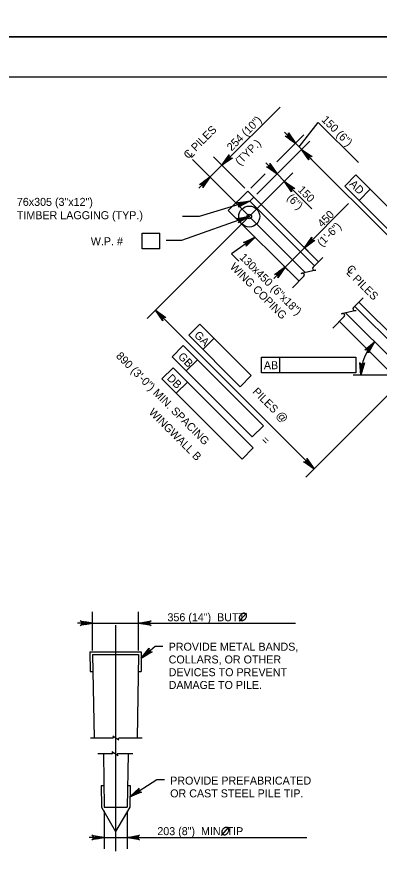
# Model space of a CAD drawing. Extents: x 635440 to 640306, y 296653 to 298484.
# Drawn here: x 638479.7 to 638615.6, y 296941.7 to 297255 of the extents above; entities that cross this region are included whole.
import ezdxf

# ---------------------------------------------------------------- set-up
doc = ezdxf.new("R2010")
doc.units = 0
for name, color, linetype in [('2', 7, 'Continuous'), ('4', 7, 'Continuous'), ('5', 7, 'Continuous'), ('52', 7, 'Continuous'), ('PLT-BNDY', 7, 'Continuous')]:
    doc.layers.add(name, color=color, linetype=linetype)

msp = doc.modelspace()

# ---------------------------------------------------------------- linework, layer by layer
at = {"layer": '2'}
for p, q in [((638475.46, 297232.46), (639261.46, 297232.46)), ((638566.31, 297189.6), (638559, 297182.3)), ((638592.81, 297163.11), (638566.31, 297189.6)), ((638585.5, 297155.8), (638559, 297182.3)), ((638627.92, 297128), (638607.92, 297148)), ((638623.64, 297117.66), (638600.61, 297140.69))]:
    msp.add_line(p, q, dxfattribs=at)
at = {"layer": '4'}
for p, q in [((638568.57, 297187.34), (638567.01, 297185.78)), ((638591.24, 297161.54), (638567.01, 297185.78)), ((638632.09, 297120.7), (638606.35, 297146.43)), ((638516.77, 297026.87), (638516.77, 296942.2)), ((638507.15, 297016.86), (638507.27, 297009.46)), ((638507.15, 297016.86), (638526.39, 297016.86)), ((638508.15, 297015.87), (638508.65, 296984.5)), ((638508.15, 297015.87), (638525.39, 297015.87)), ((638525.39, 297015.87), (638524.89, 296984.5)), ((638526.39, 297016.86), (638526.27, 297009.46)), ((638507.27, 297009.46), (638508.25, 297009.46)), ((638525.29, 297009.46), (638526.27, 297009.46)), ((638515.67, 296984.5), (638507.3, 296984.5)), ((638517.98, 296983.77), (638515.67, 296985.23)), ((638526.66, 296984.5), (638518, 296984.5)), ((638515.36, 296978.66), (638510.07, 296978.66)), ((638512.15, 296978.66), (638512.46, 296958.69)), ((638517.67, 296977.93), (638515.36, 296979.38)), ((638523.26, 296978.66), (638517.69, 296978.66)), ((638521.4, 296978.66), (638521.08, 296958.69)), ((638511.38, 296966.73), (638511.48, 296958.68)), ((638511.38, 296966.73), (638512.37, 296966.73)), ((638521.18, 296966.73), (638522.16, 296966.73)), ((638522.16, 296966.73), (638522.06, 296958.68)), ((638511.48, 296958.68), (638516.77, 296949.51)), ((638512.46, 296958.69), (638521.08, 296958.69)), ((638522.06, 296958.68), (638516.77, 296949.51))]:
    msp.add_line(p, q, dxfattribs=at)
msp.add_circle((638566.85, 297180.05), 3.94, dxfattribs=at)
for centre, start, end in [((638515.64, 296984.84), 275.3286, 57.8672), ((638518, 296984.16), 90, 240), ((638515.33, 296979), 275.3286, 57.8672), ((638517.69, 296978.32), 90, 240)]:
    msp.add_arc(centre, 0.341, start, end, dxfattribs=at)
at = {"layer": '5'}
for p, q in [((638556.62, 297199.29), (638578.4, 297221.08)), ((638585.54, 297206.15), (638592.72, 297215.34)), ((638592.72, 297215.34), (638607.78, 297200.28)), ((638577.21, 297200.51), (638587.33, 297210.62)), ((638584.19, 297207.49), (638580.02, 297211.67)), ((638569.66, 297188.43), (638589.59, 297208.36)), ((638589.41, 297202.27), (638584.19, 297207.49)), ((638645.8, 297145.88), (638586.46, 297205.23)), ((638587.84, 297159.07), (638545.53, 297201.37)), ((638565.22, 297190.69), (638553.49, 297202.43)), ((638577.25, 297196.02), (638573.08, 297200.2)), ((638589.24, 297202.44), (638591.33, 297200.36)), ((638552.11, 297194.79), (638556.62, 297199.3)), ((638569.66, 297188.43), (638580.38, 297199.16)), ((638583.17, 297196.37), (638528.58, 297141.78)), ((638552.11, 297194.79), (638547.94, 297190.62)), ((638567.4, 297190.69), (638572.82, 297196.11)), ((638577.25, 297196.02), (638580.04, 297193.24)), ((638606.81, 297195.62), (638602.64, 297191.45)), ((638606.81, 297195.62), (638636.88, 297165.56)), ((638580.04, 297193.24), (638590.32, 297182.96)), ((638602.64, 297191.45), (638632.7, 297161.38)), ((638612.16, 297190.28), (638607.98, 297186.1)), ((638587.56, 297168.36), (638604.09, 297184.89)), ((638526.74, 297167.95), (638526.74, 297173.85)), ((638526.74, 297173.85), (638533.33, 297173.85)), ((638533.33, 297167.95), (638533.33, 297173.85)), ((638533.33, 297167.95), (638526.74, 297167.95)), ((638580.25, 297161.05), (638587.56, 297168.36)), ((638587.12, 297168.8), (638590.69, 297165.22)), ((638594.37, 297164.67), (638590.78, 297161.08)), ((638594.37, 297164.67), (638590.78, 297161.08)), ((638580.25, 297161.05), (638576.08, 297156.87)), ((638579.81, 297161.49), (638583.38, 297157.92)), ((638587.34, 297157.65), (638583.02, 297153.32)), ((638587.34, 297157.65), (638583.02, 297153.32)), ((638609.48, 297149.56), (638605.9, 297145.98)), ((638609.48, 297149.56), (638605.9, 297145.98)), ((638591.15, 297085.47), (638531.71, 297144.91)), ((638628.51, 297118.39), (638602.94, 297143.96)), ((638602.47, 297142.54), (638598.14, 297138.22)), ((638602.47, 297142.54), (638598.14, 297138.22)), ((638548.32, 297139.75), (638544.15, 297135.57)), ((638548.32, 297139.75), (638567.62, 297120.45)), ((638544.15, 297135.57), (638563.44, 297116.27)), ((638542.08, 297131.69), (638537.91, 297127.51)), ((638542.08, 297131.69), (638572.15, 297101.62)), ((638553.67, 297134.4), (638549.49, 297130.23)), ((638537.91, 297127.51), (638567.97, 297097.44)), ((638547.43, 297126.34), (638543.25, 297122.16)), ((638571.46, 297127.36), (638606.77, 297127.36)), ((638571.46, 297121.45), (638571.46, 297127.36)), ((638578.31, 297121.45), (638578.31, 297127.36)), ((638606.77, 297127.36), (638606.77, 297121.45)), ((638538.31, 297123.35), (638534.13, 297119.17)), ((638538.31, 297123.35), (638568.37, 297093.28)), ((638534.13, 297119.17), (638564.2, 297089.1)), ((638567.62, 297120.45), (638563.44, 297116.27)), ((638606.77, 297121.45), (638571.46, 297121.45)), ((638625.2, 297119.53), (638588.01, 297082.34)), ((638898.7, 297120.62), (638605.79, 297120.62)), ((638543.65, 297118), (638539.48, 297113.82)), ((638572.15, 297101.62), (638567.97, 297097.44)), ((638568.37, 297093.28), (638564.2, 297089.1)), ((638508.15, 297017.35), (638508.15, 297031.87)), ((638525.39, 297017.35), (638525.39, 297031.87)), ((638563.03, 297028.31), (638565.83, 297031.37)), ((638508.15, 297027.61), (638502.48, 297027.61)), ((638508.15, 297027.61), (638584.13, 297027.61)), ((638525.39, 297027.61), (638531.06, 297027.61)), ((638526.35, 297014.47), (638531.62, 297019.03)), ((638531.62, 297019.03), (638534.45, 297019.03)), ((638522.11, 296962.48), (638532.19, 296968.97)), ((638532.19, 296968.97), (638535.02, 296968.97)), ((638512.46, 296957.22), (638512.46, 296942.97)), ((638521.08, 296957.22), (638521.08, 296942.97)), ((638556.44, 296948.03), (638559.24, 296951.1)), ((638512.46, 296947.23), (638506.79, 296947.23)), ((638512.46, 296947.23), (638588.38, 296947.23)), ((638523.91, 296947.23), (638526.75, 296947.23))]:
    msp.add_line(p, q, dxfattribs=at)
for points in [[(638584.19, 297207.49), (638580.28, 297210.17), (638580.71, 297210.09), (638581.06, 297210.18), (638581.32, 297210.36), (638581.5, 297210.62), (638581.59, 297210.97), (638581.52, 297211.4), (638584.19, 297207.49), (638581.59, 297210.97), (638581.5, 297210.62), (638584.19, 297207.49), (638581.32, 297210.36), (638581.06, 297210.18), (638584.19, 297207.49), (638580.71, 297210.09)], [(638586.46, 297205.23), (638590.37, 297202.55), (638589.94, 297202.63), (638589.59, 297202.54), (638589.33, 297202.35), (638589.15, 297202.1), (638589.06, 297201.74), (638589.13, 297201.31), (638586.46, 297205.23), (638589.06, 297201.74), (638589.15, 297202.1), (638586.46, 297205.23), (638589.33, 297202.35), (638589.59, 297202.54), (638586.46, 297205.23), (638589.94, 297202.63)], [(638556.62, 297199.29), (638559.3, 297203.21), (638559.22, 297202.78), (638559.31, 297202.43), (638559.49, 297202.17), (638559.75, 297201.98), (638560.1, 297201.9), (638560.53, 297201.97), (638556.62, 297199.29), (638560.1, 297201.9), (638559.75, 297201.98), (638556.62, 297199.29), (638559.49, 297202.17), (638559.31, 297202.43), (638556.62, 297199.29), (638559.22, 297202.78)], [(638577.25, 297196.02), (638573.34, 297198.7), (638573.77, 297198.62), (638574.12, 297198.71), (638574.38, 297198.9), (638574.56, 297199.16), (638574.65, 297199.51), (638574.57, 297199.94), (638577.25, 297196.02), (638574.65, 297199.51), (638574.56, 297199.16), (638577.25, 297196.02), (638574.38, 297198.9), (638574.12, 297198.71), (638577.25, 297196.02), (638573.77, 297198.62)], [(638552.11, 297194.79), (638549.44, 297190.88), (638549.52, 297191.31), (638549.42, 297191.66), (638549.24, 297191.92), (638548.98, 297192.1), (638548.63, 297192.19), (638548.2, 297192.11), (638552.11, 297194.79), (638548.63, 297192.19), (638548.98, 297192.1), (638552.11, 297194.79), (638549.24, 297191.92), (638549.42, 297191.66), (638552.11, 297194.79), (638549.52, 297191.31)], [(638580.04, 297193.24), (638583.95, 297190.56), (638583.52, 297190.64), (638583.17, 297190.55), (638582.91, 297190.37), (638582.72, 297190.11), (638582.64, 297189.75), (638582.71, 297189.33), (638580.04, 297193.24), (638582.64, 297189.75), (638582.72, 297190.11), (638580.04, 297193.24), (638582.91, 297190.37), (638583.17, 297190.55), (638580.04, 297193.24), (638583.52, 297190.64)], [(638567.01, 297185.78), (638548.13, 297180.02), (638541.79, 297180.02)], [(638567.01, 297185.78), (638562.8, 297183.58), (638563.07, 297183.93), (638563.16, 297184.28), (638563.12, 297184.59), (638562.98, 297184.88), (638562.71, 297185.12), (638562.29, 297185.25), (638567.01, 297185.78), (638562.71, 297185.12), (638562.98, 297184.88), (638567.01, 297185.78), (638563.12, 297184.59), (638563.16, 297184.28), (638567.01, 297185.78), (638563.07, 297183.93)], [(638566.85, 297180.05), (638541.5, 297171.03), (638535.7, 297171.03)], [(638566.85, 297180.05), (638562.75, 297177.67), (638563.01, 297178.02), (638563.08, 297178.38), (638563.02, 297178.69), (638562.87, 297178.97), (638562.59, 297179.2), (638562.17, 297179.31), (638566.85, 297180.05), (638562.59, 297179.2), (638562.87, 297178.97), (638566.85, 297180.05), (638563.02, 297178.69), (638563.08, 297178.38), (638566.85, 297180.05), (638563.01, 297178.02)], [(638569, 297172.3), (638560.21, 297166.07), (638562.99, 297163.3)], [(638587.56, 297168.36), (638590.24, 297172.27), (638590.16, 297171.84), (638590.25, 297171.49), (638590.43, 297171.23), (638590.69, 297171.05), (638591.04, 297170.96), (638591.47, 297171.03), (638587.56, 297168.36), (638591.04, 297170.96), (638590.69, 297171.05), (638587.56, 297168.36), (638590.43, 297171.23), (638590.25, 297171.49), (638587.56, 297168.36), (638590.16, 297171.84)], [(638580.25, 297161.05), (638577.57, 297157.13), (638577.65, 297157.56), (638577.56, 297157.92), (638577.38, 297158.17), (638577.12, 297158.36), (638576.77, 297158.45), (638576.34, 297158.37), (638580.25, 297161.05), (638576.77, 297158.45), (638577.12, 297158.36), (638580.25, 297161.05), (638577.38, 297158.17), (638577.56, 297157.92), (638580.25, 297161.05), (638577.65, 297157.56)], [(638591.46, 297159.89), (638591.81, 297159.97), (638586.27, 297158.71), (638586.64, 297158.79)], [(638591.46, 297159.89), (638591.81, 297159.97), (638586.27, 297158.71), (638586.64, 297158.79)], [(638531.71, 297144.91), (638535.62, 297142.23), (638535.19, 297142.31), (638534.84, 297142.22), (638534.58, 297142.04), (638534.4, 297141.78), (638534.31, 297141.43), (638534.39, 297141), (638531.71, 297144.91), (638534.31, 297141.43), (638534.4, 297141.78), (638531.71, 297144.91), (638534.58, 297142.04), (638534.84, 297142.22), (638531.71, 297144.91), (638535.19, 297142.31)], [(638606.58, 297144.79), (638606.93, 297144.87), (638601.39, 297143.6), (638601.76, 297143.69)], [(638606.58, 297144.79), (638606.93, 297144.87), (638601.39, 297143.6), (638601.76, 297143.69)], [(638613.84, 297133.07), (638611.5, 297128.94), (638611.54, 297129.38), (638611.42, 297129.72), (638611.22, 297129.96), (638610.95, 297130.12), (638610.59, 297130.18), (638610.16, 297130.07), (638613.84, 297133.07), (638610.59, 297130.18), (638610.95, 297130.12), (638613.84, 297133.07), (638611.22, 297129.96), (638611.42, 297129.72), (638613.84, 297133.07), (638611.54, 297129.38)], [(638608.64, 297120.61), (638608.25, 297125.34), (638608.46, 297124.95), (638608.75, 297124.74), (638609.06, 297124.65), (638609.37, 297124.67), (638609.7, 297124.82), (638609.99, 297125.16), (638608.64, 297120.61), (638609.7, 297124.82), (638609.37, 297124.67), (638608.64, 297120.61), (638609.06, 297124.65), (638608.75, 297124.74), (638608.64, 297120.61), (638608.46, 297124.95)], [(638591.15, 297085.47), (638587.23, 297088.15), (638587.66, 297088.07), (638588.01, 297088.16), (638588.27, 297088.35), (638588.46, 297088.6), (638588.55, 297088.96), (638588.47, 297089.39), (638591.15, 297085.47), (638588.55, 297088.96), (638588.46, 297088.6), (638591.15, 297085.47), (638588.27, 297088.35), (638588.01, 297088.16), (638591.15, 297085.47), (638587.66, 297088.07)], [(638508.15, 297027.61), (638503.49, 297026.74), (638503.85, 297026.99), (638504.04, 297027.3), (638504.09, 297027.61), (638504.04, 297027.93), (638503.85, 297028.24), (638503.49, 297028.49), (638508.15, 297027.61), (638503.85, 297028.24), (638504.04, 297027.93), (638508.15, 297027.61), (638504.09, 297027.61), (638504.04, 297027.3), (638508.15, 297027.61), (638503.85, 297026.99)], [(638525.39, 297027.61), (638530.05, 297028.49), (638529.69, 297028.24), (638529.5, 297027.93), (638529.45, 297027.61), (638529.5, 297027.3), (638529.69, 297026.99), (638530.05, 297026.74), (638525.39, 297027.61), (638529.69, 297026.99), (638529.5, 297027.3), (638525.39, 297027.61), (638529.45, 297027.61), (638529.5, 297027.93), (638525.39, 297027.61), (638529.69, 297028.24)], [(638526.35, 297014.47), (638529.3, 297018.18), (638529.19, 297017.76), (638529.26, 297017.41), (638529.42, 297017.13), (638529.67, 297016.93), (638530.01, 297016.82), (638530.45, 297016.86), (638526.35, 297014.47), (638530.01, 297016.82), (638529.67, 297016.93), (638526.35, 297014.47), (638529.42, 297017.13), (638529.26, 297017.41), (638526.35, 297014.47), (638529.19, 297017.76)], [(638522.11, 296962.48), (638525.55, 296965.74), (638525.39, 296965.33), (638525.4, 296964.97), (638525.52, 296964.68), (638525.74, 296964.44), (638526.06, 296964.28), (638526.5, 296964.27), (638522.11, 296962.48), (638526.06, 296964.28), (638525.74, 296964.44), (638522.11, 296962.48), (638525.52, 296964.68), (638525.4, 296964.97), (638522.11, 296962.48), (638525.39, 296965.33)], [(638512.46, 296947.23), (638507.8, 296946.35), (638508.16, 296946.6), (638508.34, 296946.91), (638508.4, 296947.23), (638508.34, 296947.54), (638508.16, 296947.85), (638507.8, 296948.1), (638512.46, 296947.23), (638508.16, 296947.85), (638508.34, 296947.54), (638512.46, 296947.23), (638508.4, 296947.23), (638508.34, 296946.91), (638512.46, 296947.23), (638508.16, 296946.6)], [(638521.08, 296947.23), (638525.74, 296948.1), (638525.38, 296947.85), (638525.2, 296947.54), (638525.14, 296947.23), (638525.2, 296946.91), (638525.38, 296946.6), (638525.74, 296946.35), (638521.08, 296947.23), (638525.38, 296946.6), (638525.2, 296946.91), (638521.08, 296947.23), (638525.14, 296947.23), (638525.2, 296947.54), (638521.08, 296947.23), (638525.38, 296947.85)]]:
    msp.add_lwpolyline(points, dxfattribs=at)
for points in [[(638582.45, 297209.92), (638581.76, 297209.23), (638584.19, 297207.49)], [(638588.89, 297203.49), (638588.2, 297202.79), (638586.46, 297205.23)], [(638558.36, 297201.73), (638559.06, 297201.04), (638556.62, 297199.3)], [(638575.51, 297198.46), (638574.82, 297197.76), (638577.25, 297196.02)], [(638549.68, 297193.05), (638550.37, 297192.36), (638552.11, 297194.79)], [(638582.47, 297191.5), (638581.77, 297190.8), (638580.04, 297193.24)], [(638567.01, 297185.78), (638564.11, 297185.15), (638564.25, 297184.68)], [(638566.85, 297180.05), (638563.99, 297179.3), (638564.15, 297178.83)], [(638589.3, 297170.79), (638590, 297170.1), (638587.56, 297168.36)], [(638577.82, 297159.31), (638578.51, 297158.61), (638580.25, 297161.05)], [(638534.14, 297143.17), (638533.45, 297142.48), (638531.71, 297144.91)], [(638589.41, 297087.91), (638588.71, 297087.21), (638591.15, 297085.47)], [(638505.32, 297028.09), (638505.32, 297027.14), (638508.15, 297027.61)], [(638528.22, 297028.09), (638528.22, 297027.14), (638525.39, 297027.61)], [(638528.8, 297015.97), (638528.18, 297016.69), (638526.35, 297014.47)], [(638524.76, 296963.63), (638524.25, 296964.42), (638522.12, 296962.49)], [(638509.63, 296947.7), (638509.63, 296946.76), (638512.46, 296947.23)], [(638523.91, 296947.7), (638523.91, 296946.76), (638521.08, 296947.23)]]:
    msp.add_lwpolyline(points, close=True, dxfattribs=at)
msp.add_circle((638566.85, 297180.05), 0.85, dxfattribs=at)
for centre, radius, start, end in [((638591.28, 297160.58), 0.71, 135, 285), ((638591.28, 297160.58), 0.71, 135, 285), ((638586.8, 297158.1), 0.71, 320.3286, 102.8672), ((638586.8, 297158.1), 0.71, 320.3286, 102.8672), ((638606.4, 297145.48), 0.71, 135, 285), ((638606.4, 297145.48), 0.71, 135, 285), ((638601.92, 297143), 0.71, 320.3286, 102.8672), ((638601.92, 297143), 0.71, 320.3286, 102.8672), ((638626.16, 297120.62), 17.52, 134.7007, 179.9991)]:
    msp.add_arc(centre, radius, start, end, dxfattribs=at)
for points in [[(638565.54, 297031.07), (638565.32, 297031.24), (638565.1, 297031.3), (638564.83, 297031.32), (638564.67, 297031.32), (638564.4, 297031.26), (638564.15, 297031.15), (638563.98, 297031.05), (638563.65, 297030.79), (638563.39, 297030.45), (638563.23, 297030.14), (638563.14, 297029.84), (638563.12, 297029.57), (638563.14, 297029.34), (638563.26, 297029.02), (638563.38, 297028.84), (638563.62, 297028.66), (638563.98, 297028.57), (638564.39, 297028.59), (638564.91, 297028.82), (638565.29, 297029.15), (638565.58, 297029.55), (638565.77, 297029.97), (638565.83, 297030.42), (638565.75, 297030.72), (638565.55, 297031.07)], [(638558.95, 296950.8), (638558.73, 296950.97), (638558.51, 296951.03), (638558.24, 296951.05), (638558.08, 296951.05), (638557.81, 296950.99), (638557.56, 296950.88), (638557.39, 296950.78), (638557.06, 296950.51), (638556.8, 296950.18), (638556.64, 296949.86), (638556.56, 296949.57), (638556.53, 296949.3), (638556.56, 296949.07), (638556.67, 296948.74), (638556.79, 296948.57), (638557.03, 296948.39), (638557.39, 296948.3), (638557.8, 296948.31), (638558.32, 296948.55), (638558.71, 296948.88), (638558.99, 296949.28), (638559.18, 296949.69), (638559.24, 296950.15), (638559.16, 296950.45), (638558.96, 296950.8)]]:
    msp.add_spline(points, degree=3, dxfattribs=at)
at = {"layer": '52'}
msp.add_lwpolyline([(638569, 297172.3), (638565.7, 297168.89), (638565.85, 297169.3), (638565.82, 297169.67), (638565.68, 297169.95), (638565.46, 297170.17), (638565.13, 297170.32), (638564.69, 297170.32), (638569, 297172.3), (638565.13, 297170.32), (638565.46, 297170.17), (638569, 297172.3), (638565.68, 297169.95), (638565.82, 297169.67), (638569, 297172.3), (638565.85, 297169.3)], dxfattribs=at)
at = {"layer": 'PLT-BNDY'}
for points in [[(638435.46, 297841.46), (639276.46, 297841.46), (639276.46, 297247.46), (638435.46, 297247.46)], [(638435.46, 297247.46), (639276.46, 297247.46), (639276.46, 296653.46), (638435.46, 296653.46)]]:
    msp.add_lwpolyline(points, close=True, dxfattribs=at)

# ---------------------------------------------------------------- texts
at = {"layer": '5'}
for s, height, rotation, p in [('254 (10")', 3, 45, (638560.22, 297204.37)), ('150 (6")', 3, 315, (638593.75, 297216.09)), ('C PILES', 3, 45, (638544.01, 297201.43)), ('(TYP.)', 3, 45, (638563.31, 297199.03)), ('L', 3, 45, (638545.1, 297201.75)), ('150', 3, 315, (638584.81, 297189.83)), ('AD', 3, 314.9382, (638604.15, 297191.99)), ('(6")', 3, 315, (638580.75, 297186.82)), ('450', 3, 45, (638594.2, 297175.79)), ('(1\'-6")', 3, 45, (638594.05, 297168.57)), ('130x450 (6"x18")', 3.0001, 315, (638562.95, 297164.49)), ('WING COPING', 3.0001, 315, (638559.41, 297160.96)), ('L PILES', 3, 315, (638603.01, 297158.84)), ('C', 3, 315, (638603.07, 297160.16)), ('GA', 3, 314.9382, (638545.98, 297135.35)), ('890 (3\'-0") MIN. SPACING', 3.0001, 315, (638516.69, 297127.51)), ('GB', 3, 314.9382, (638539.91, 297127.31)), ('DB', 3, 314.9382, (638535.79, 297119.19)), ('PILES @', 3, 314.9382, (638567.87, 297114.14)), ('WINGWALL B', 3, 315, (638528.96, 297106.36)), ('=', 3, 314.9382, (638571.1, 297096.01))]:
    msp.add_text(s, height=height, rotation=rotation, dxfattribs=at).set_placement(p)
for s, height, p in [('76x305 (3"x12")', 3.0001, (638479.74, 297184.04)), ('TIMBER LAGGING (TYP.)', 3.0001, (638479.74, 297179.04)), ('W.P. # ', 3, (638507.45, 297169.27)), ('AB', 3, (638572.32, 297122.81)), ('356 (14")  BUTT', 3.0001, (638536.19, 297028.33)), ('PROVIDE METAL BANDS,', 3.0001, (638536.64, 297017.29)), ('COLLARS, OR OTHER ', 3.0001, (638536.64, 297012.51)), ('DEVICES TO PREVENT', 3.0001, (638536.64, 297007.73)), ('DAMAGE TO PILE.', 3.0001, (638536.64, 297002.95)), ('PROVIDE PREFABRICATED', 3.0001, (638537.21, 296967.09)), ('OR CAST STEEL PILE TIP.', 3.0001, (638537.21, 296962.31)), ('203 (8")  MIN. TIP', 3.0001, (638532.39, 296948.14))]:
    msp.add_text(s, height=height, dxfattribs=at).set_placement(p)

doc.saveas('drawing.dxf')
